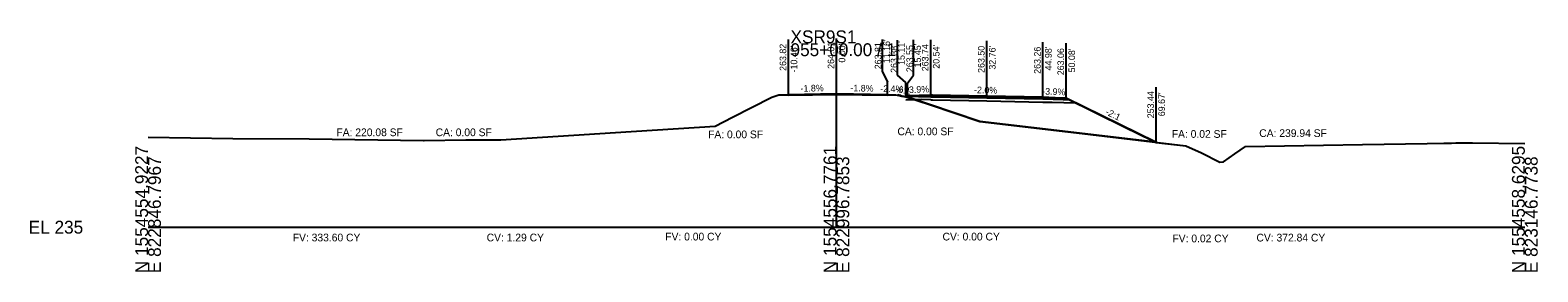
# Model space of a CAD drawing. Extents: x -26 to 823017, y -16 to 1558356.
# Drawn here: x -25.7 to 302.8, y 2990.3 to 3042.8 of the extents above; entities that cross this region are included whole.
import ezdxf

# ---------------------------------------------------------------- set-up
doc = ezdxf.new("R2010")
doc.units = 0
for name, color, linetype in [('ASPHALT_19MM1', 7, 'Continuous'), ('CONST_DCH', 7, 'Continuous'), ('CONST_LV3', 7, 'Continuous'), ('Draft_XS_Grid', 7, 'Continuous'), ('DTM_CORRIDOR', 7, 'Continuous'), ('DTM_P_FINISHED_GRADE2', 7, 'Continuous'), ('DTM_TEMP_DROP', 7, 'Continuous'), ('DTM_X_GROUND', 7, 'Continuous'), ('PROFILES_DCH_2', 7, 'Continuous'), ('XS_CELL', 7, 'Continuous'), ('XS_P_ASPHALT', 7, 'Continuous'), ('XS_P_DR_GRAVEL', 7, 'Continuous'), ('XS_P_GROUND', 7, 'Continuous'), ('XS_P_SHOULDER', 7, 'Continuous'), ('XS_P_SUBGRADE_GRANULAR', 7, 'Continuous'), ('XS_P_SUBGRADE_LEVELING', 7, 'Continuous'), ('XS_P_SUBGRADE_MILLING', 7, 'Continuous'), ('XS_P_SUBGRADE_UNDERCUT', 7, 'Continuous'), ('XS_P_TX_CLEARZONE', 7, 'Continuous'), ('XS_P_TX_FS_BS', 7, 'Continuous'), ('XS_SHEET_EW_TX_AREA', 7, 'Continuous'), ('XS_SHEET_EW_TX_VOLUME', 7, 'Continuous')]:
    doc.layers.add(name, color=color, linetype=linetype)

msp = doc.modelspace()

# ---------------------------------------------------------------- linework, layer by layer
at = {"layer": 'ASPHALT_19MM1'}
msp.add_lwpolyline([(170.54, 3028.37), (170.92, 3028.36), (182.76, 3028.13), (194.98, 3027.89), (194.98, 3028.1), (182.76, 3028.34), (170.92, 3028.57), (170.54, 3028.58), (170.54, 3028.37)], dxfattribs=at)
at = {"layer": 'CONST_DCH'}
msp.add_lwpolyline([(170.54, 3028.58), (170.92, 3028.57), (182.76, 3028.34), (194.98, 3028.1), (194.98, 3028.26), (182.76, 3028.5), (170.92, 3028.74), (170.54, 3028.74), (170.54, 3028.58)], dxfattribs=at)
at = {"layer": 'CONST_LV3'}
for points in [[(0, 3019.59), (18.49, 3019.29), (35.12, 3019.19), (59.99, 3018.89), (60.13, 3018.85), (69.23, 3019), (76.87, 3019.02), (101.86, 3020.6), (123.55, 3021.99), (127.36, 3023.93), (135.75, 3028.21), (135.95, 3028.28), (137.42, 3028.78), (139.54, 3028.82), (139.54, 3028.82)], [(150, 3029.01), (164, 3028.73)], [(161.16, 3028.81), (161.16, 3028.81), (162.9, 3028.78), (164.22, 3028.53), (165.11, 3028.38), (165.11, 3028.38), (165.13, 3028.39), (165.45, 3028.55), (168.61, 3028.67), (170.54, 3028.74), (170.92, 3028.74), (181.75, 3028.52), (182.76, 3028.5), (192.92, 3028.3), (194.98, 3028.26), (198.97, 3028.1), (200.08, 3028.06), (212.86, 3021.79), (215.65, 3020.41), (217.04, 3019.73), (219.67, 3018.44), (220.89, 3018.3), (226.14, 3017.69), (229.52, 3016.15), (233.52, 3014.17), (234.35, 3014.22), (236.79, 3015.97), (239.11, 3017.57), (264.63, 3017.99), (278.75, 3018.22), (282.38, 3018.28), (284.04, 3018.31), (284.99, 3018.33), (288.59, 3018.35), (300, 3018.22)], [(163.36, 3028.76), (164, 3028.73), (164, 3028.73)], [(165.11, 3028.38), (165.13, 3028.39), (165.45, 3028.55), (168.61, 3028.67), (170.54, 3028.74)], [(200.08, 3028.06), (218.42, 3019.05), (219.62, 3018.46)]]:
    msp.add_lwpolyline(points, dxfattribs=at)
at = {"layer": 'DTM_P_FINISHED_GRADE2'}
msp.add_lwpolyline([(139.54, 3028.82), (150, 3029.01), (161.16, 3028.81)], dxfattribs=at)
at = {"layer": 'DTM_X_GROUND'}
for points in [[(0, 3019.59), (18.49, 3019.29), (35.12, 3019.19), (59.99, 3018.89), (60.13, 3018.85), (69.23, 3019), (76.87, 3019.02), (101.86, 3020.6), (123.55, 3021.99), (127.36, 3023.93), (135.75, 3028.21), (135.95, 3028.28), (137.42, 3028.78), (146.81, 3028.96), (150.24, 3029.02), (153.38, 3028.96), (162.9, 3028.78), (164.22, 3028.53), (165.18, 3028.37), (165.36, 3028.32), (175.62, 3024.89), (181.24, 3023), (198.02, 3021.03), (226.14, 3017.69), (229.52, 3016.15), (233.52, 3014.17), (234.35, 3014.22), (236.79, 3015.97), (239.11, 3017.57), (264.63, 3017.99), (278.75, 3018.22), (282.38, 3018.28), (284.04, 3018.31), (284.99, 3018.33), (288.59, 3018.35), (300, 3018.22)], [(0, 3019.59), (18.49, 3019.29), (35.12, 3019.19), (59.99, 3018.89), (60.13, 3018.85), (69.23, 3019), (76.87, 3019.02), (101.86, 3020.6), (123.55, 3021.99), (127.36, 3023.93), (135.75, 3028.21), (135.95, 3028.28), (137.42, 3028.78), (146.81, 3028.96), (150.24, 3029.02), (153.38, 3028.96), (162.9, 3028.78), (164.22, 3028.53), (165.11, 3028.38), (165.11, 3028.38), (165.13, 3028.39), (165.45, 3028.55), (168.61, 3028.67), (170.54, 3028.74), (170.92, 3028.74), (181.75, 3028.52), (182.76, 3028.5), (192.92, 3028.3), (194.98, 3028.26), (198.97, 3028.1), (200.08, 3028.06), (212.86, 3021.79), (215.65, 3020.41), (217.04, 3019.73), (219.67, 3018.44), (220.89, 3018.3), (226.14, 3017.69), (229.52, 3016.15), (233.52, 3014.17), (234.35, 3014.22), (236.79, 3015.97), (239.11, 3017.57), (264.63, 3017.99), (278.75, 3018.22), (282.38, 3018.28), (284.04, 3018.31), (284.99, 3018.33), (288.59, 3018.35), (300, 3018.22)], [(0, 3019.59), (18.49, 3019.29), (35.12, 3019.19), (59.99, 3018.89), (60.13, 3018.85), (69.23, 3019), (76.87, 3019.02), (101.86, 3020.6), (123.55, 3021.99), (127.36, 3023.93), (135.75, 3028.21), (135.95, 3028.28), (137.42, 3028.78), (139.54, 3028.82), (139.54, 3028.82), (150, 3029.01), (150, 3029.01), (150, 3029.01), (150, 3029.01), (150, 3029.01), (150, 3029.01), (150, 3029.01), (161.16, 3028.81), (161.16, 3028.81), (161.16, 3028.81), (162.9, 3028.78), (164.22, 3028.53), (165.11, 3028.38), (165.11, 3028.38), (165.13, 3028.39), (165.45, 3028.55), (168.61, 3028.67), (170.54, 3028.74), (170.92, 3028.74), (181.75, 3028.52), (182.76, 3028.5), (192.92, 3028.3), (194.98, 3028.26), (198.97, 3028.1), (200.08, 3028.06), (212.86, 3021.79), (215.65, 3020.41), (217.04, 3019.73), (219.67, 3018.44), (220.89, 3018.3), (226.14, 3017.69), (229.52, 3016.15), (233.52, 3014.17), (234.35, 3014.22), (236.79, 3015.97), (239.11, 3017.57), (264.63, 3017.99), (278.75, 3018.22), (282.38, 3018.28), (284.04, 3018.31), (284.99, 3018.33), (288.59, 3018.35), (300, 3018.22)]]:
    msp.add_lwpolyline(points, dxfattribs=at)
at = {"layer": 'XS_CELL'}
for p, q in [((150, 3000), (150, 3040)), ((0, 3000), (150, 3000)), ((150, 3000), (300, 3000))]:
    msp.add_line(p, q, dxfattribs=at)
at = {"layer": 'XS_P_ASPHALT'}
msp.add_lwpolyline([(139.54, 3028.7), (150, 3028.89), (150, 3028.89), (161.16, 3028.69), (161.16, 3028.69), (161.16, 3028.81), (161.16, 3028.81), (150, 3029.01), (150, 3029.01), (139.54, 3028.82), (139.54, 3028.7)], dxfattribs=at)
at = {"layer": 'XS_P_DR_GRAVEL'}
for points in [[(168.61, 3028.67), (165.45, 3028.55), (165.32, 3028.48), (165.31, 3028.47), (167.91, 3028.42), (170.54, 3028.37), (170.54, 3028.72), (170.54, 3028.74), (168.61, 3028.67)], [(198.97, 3028.1), (194.98, 3028.26), (194.98, 3027.96), (194.98, 3027.89), (199.41, 3027.8), (200.66, 3027.77), (200.53, 3027.84), (200.08, 3028.06), (198.97, 3028.1)]]:
    msp.add_lwpolyline(points, dxfattribs=at)
at = {"layer": 'XS_P_GROUND'}
for points in [[(163.82, 3028.61), (163.36, 3028.76), (163.36, 3028.76)], [(219.62, 3018.46), (219.62, 3018.46), (219.62, 3018.46), (198.02, 3021.03), (198.02, 3021.03), (181.24, 3023), (175.62, 3024.89), (175.62, 3024.89), (165.36, 3028.32), (165.36, 3028.32), (165.18, 3028.37), (164.22, 3028.53), (164.22, 3028.53), (163.82, 3028.61), (163.82, 3028.61)], [(163.82, 3028.61), (163.82, 3028.61), (164.22, 3028.53), (164.22, 3028.53), (165.18, 3028.37), (165.36, 3028.32), (165.36, 3028.32), (175.62, 3024.89), (175.62, 3024.89), (181.24, 3023), (198.02, 3021.03), (198.02, 3021.03), (219.62, 3018.46), (219.62, 3018.46), (219.62, 3018.46)], [(165.45, 3028.55), (165.11, 3028.38)], [(200.08, 3028.06), (219.67, 3018.44)]]:
    msp.add_lwpolyline(points, dxfattribs=at)
at = {"layer": 'XS_P_SHOULDER'}
for points in [[(165.45, 3028.55), (168.61, 3028.67), (170.54, 3028.74)], [(200.08, 3028.06), (198.97, 3028.1), (194.98, 3028.26)]]:
    msp.add_lwpolyline(points, dxfattribs=at)
at = {"layer": 'XS_P_SUBGRADE_GRANULAR'}
for points in [[(170.54, 3027.7), (168.51, 3027.74), (165.12, 3027.61)], [(170.54, 3027.7), (170.92, 3027.7), (182.76, 3027.46)], [(182.76, 3027.46), (194.98, 3027.22)], [(194.98, 3027.22), (197.02, 3027.18), (202.08, 3027.08)]]:
    msp.add_lwpolyline(points, dxfattribs=at)
at = {"layer": 'XS_P_SUBGRADE_LEVELING'}
msp.add_lwpolyline([(139.54, 3028.7), (146.81, 3028.83), (146.81, 3028.83), (150, 3028.89), (150.24, 3028.88), (153.38, 3028.83), (153.38, 3028.83), (161.16, 3028.69), (161.16, 3028.69)], dxfattribs=at)
msp.add_lwpolyline([(139.54, 3028.7), (146.81, 3028.83), (146.81, 3028.83), (150, 3028.89), (150.24, 3028.88), (153.38, 3028.83), (153.38, 3028.83), (161.16, 3028.69), (161.16, 3028.69)], dxfattribs=at)
at = {"layer": 'XS_P_SUBGRADE_MILLING'}
msp.add_lwpolyline([(161.16, 3028.81), (161.16, 3028.81), (161.16, 3028.69), (161.16, 3028.69), (153.38, 3028.83), (153.38, 3028.83), (150.24, 3028.88), (150, 3028.89), (146.81, 3028.83), (146.81, 3028.83), (139.54, 3028.7), (139.54, 3028.82), (146.81, 3028.96), (146.81, 3028.96), (150, 3029.01), (150.24, 3029.02), (153.38, 3028.96), (153.38, 3028.96), (161.16, 3028.81)], dxfattribs=at)
at = {"layer": 'XS_P_SUBGRADE_UNDERCUT'}
msp.add_lwpolyline([(165.11, 3028.38), (170.49, 3026.6), (181.24, 3023), (219.62, 3018.46), (200.08, 3028.06), (192.92, 3028.3), (182.76, 3028.5), (170.54, 3028.74), (165.45, 3028.55)], close=True, dxfattribs=at)
at = {"layer": 'XS_P_TX_CLEARZONE'}
for p, q in [((139.54, 3028.82), (139.54, 3040.82)), ((150, 3029.01), (150, 3041.01)), ((160.02, 3033.78), (160.02, 3040.81)), ((163.31, 3033.07), (163.31, 3040.65)), ((166.82, 3033.04), (166.82, 3040.74)), ((170.54, 3028.74), (170.54, 3040.74)), ((182.76, 3028.5), (182.76, 3040.5)), ((194.98, 3028.26), (194.98, 3040.26)), ((200.08, 3028.06), (200.08, 3040.06)), ((160.02, 3033.78), (161.16, 3031.53)), ((165.11, 3031.48), (163.31, 3033.07)), ((165.45, 3031.36), (166.82, 3033.04)), ((161.16, 3028.81), (161.16, 3031.53)), ((165.11, 3028.38), (165.11, 3031.48)), ((165.45, 3028.55), (165.45, 3031.36)), ((219.67, 3018.44), (219.67, 3030.44))]:
    msp.add_line(p, q, dxfattribs=at)

# ---------------------------------------------------------------- texts
at = {"layer": 'CONST_DCH'}
for p in [(165.04, 3028.26), (219.54, 3018.34), (219.59, 3018.32)]:
    msp.add_text('X', height=0.24, dxfattribs=at).set_placement(p)
at = {"layer": 'Draft_XS_Grid'}
msp.add_text('-', height=0.0001, dxfattribs=at).set_placement((0, 3000))
at = {"layer": 'DTM_CORRIDOR'}
for p in [(170.46, 3028.62), (182.68, 3028.38), (194.91, 3028.14)]:
    msp.add_text('X', height=0.24, dxfattribs=at).set_placement(p)
at = {"layer": 'DTM_TEMP_DROP'}
for p in [(149.92, 3028.89), (139.46, 3028.7), (161.08, 3028.69)]:
    msp.add_text('X', height=0.24, dxfattribs=at).set_placement(p)
at = {"layer": 'PROFILES_DCH_2'}
for p in [(163.28, 3028.64), (163.74, 3028.49), (219.54, 3018.34)]:
    msp.add_text('X', height=0.24, dxfattribs=at).set_placement(p)
at = {"layer": 'XS_CELL'}
for s, p in [('XSR9S1', (140, 3040)), ('955+00.00 / 1', (140, 3037.2)), ('EL 235', (-26, 2998.6))]:
    msp.add_text(s, height=2.8, dxfattribs=at).set_placement(p)
for s, p in [('N 1554554.9227', (0, 2990)), ('N 1554556.7761', (150, 2990)), ('N 1554558.6295', (300, 2990)), ('E 822846.7967', (2.8, 2990)), ('E 822996.7853', (152.8, 2990)), ('E 823146.7738', (302.8, 2990))]:
    msp.add_text(s, height=2.8, rotation=90, dxfattribs=at).set_placement(p)
at = {"layer": 'XS_P_ASPHALT'}
for p in [(165.04, 3028.26), (219.59, 3018.32)]:
    msp.add_text('X', height=0.24, dxfattribs=at).set_placement(p)
at = {"layer": 'XS_P_SHOULDER'}
for p in [(165.38, 3028.43), (200, 3027.94)]:
    msp.add_text('X', height=0.24, dxfattribs=at).set_placement(p)
at = {"layer": 'XS_P_TX_CLEARZONE'}
for s, p in [('263.82', (139.06, 3034)), ("-10.46'", (141.46, 3033.66)), ('264.01', (149.52, 3034.44)), ("0.00'", (151.92, 3035.8)), ('263.81', (159.8, 3034.35)), ("11.16'", (161.65, 3035.67)), ('263.38', (163.27, 3033.56)), ("15.11'", (164.87, 3035.3)), ('263.55', (166.69, 3033.72)), ("15.45'", (168.4, 3034.74)), ('263.74', (170.06, 3033.92)), ("20.54'", (172.46, 3034.47)), ('263.50', (182.28, 3033.56)), ("32.76'", (184.68, 3034.27)), ('263.26', (194.5, 3033.36)), ("44.98'", (196.9, 3034.1)), ('263.06', (199.6, 3033.05)), ("50.08'", (202, 3033.67)), ('253.44', (219.19, 3023.69)), ("69.67'", (221.59, 3024.14))]:
    msp.add_text(s, height=1.44, rotation=90, dxfattribs=at).set_placement(p)
at = {"layer": 'XS_P_TX_FS_BS'}
for s, rotation, p in [('-1.8%', 1.0485, (142.2, 3029.47)), ('-1.8%', 358.9603, (153.04, 3029.56)), ('-2.4%', 358.6484, (159.54, 3029.45)), ('-6:1', 349.9756, (162.75, 3029.41)), ('3.9%', 2.2454, (165.83, 3029.16)), ('-2.0%', 358.8686, (179.98, 3029.16)), ('-3.9%', 357.7444, (194.82, 3028.87)), ('-2:1', 333.8482, (208.49, 3024.6))]:
    msp.add_text(s, height=1.44, rotation=rotation, dxfattribs=at).set_placement(p)
at = {"layer": 'XS_SHEET_EW_TX_AREA'}
for s, p in [('FA: 220.08 SF', (41.04, 3019.8)), ('CA: 0.00 SF', (62.67, 3019.8)), ('FA: 0.00 SF', (122.03, 3019.35)), ('CA: 0.00 SF', (163.29, 3020)), ('FA: 0.02 SF', (223.07, 3019.44)), ('CA: 239.94 SF', (242.13, 3019.62))]:
    msp.add_text(s, height=1.68, dxfattribs=at).set_placement(p)
at = {"layer": 'XS_SHEET_EW_TX_VOLUME'}
for s, p in [('FV: 333.60 CY', (31.53, 2996.92)), ('CV: 1.29 CY', (73.78, 2996.92)), ('FV: 0.00 CY', (112.7, 2997.12)), ('CV: 0.00 CY', (173.12, 2997.12)), ('FV: 0.02 CY', (223.21, 2996.72)), ('CV: 372.84 CY', (241.53, 2996.9))]:
    msp.add_text(s, height=1.68, dxfattribs=at).set_placement(p)

doc.saveas('drawing.dxf')
